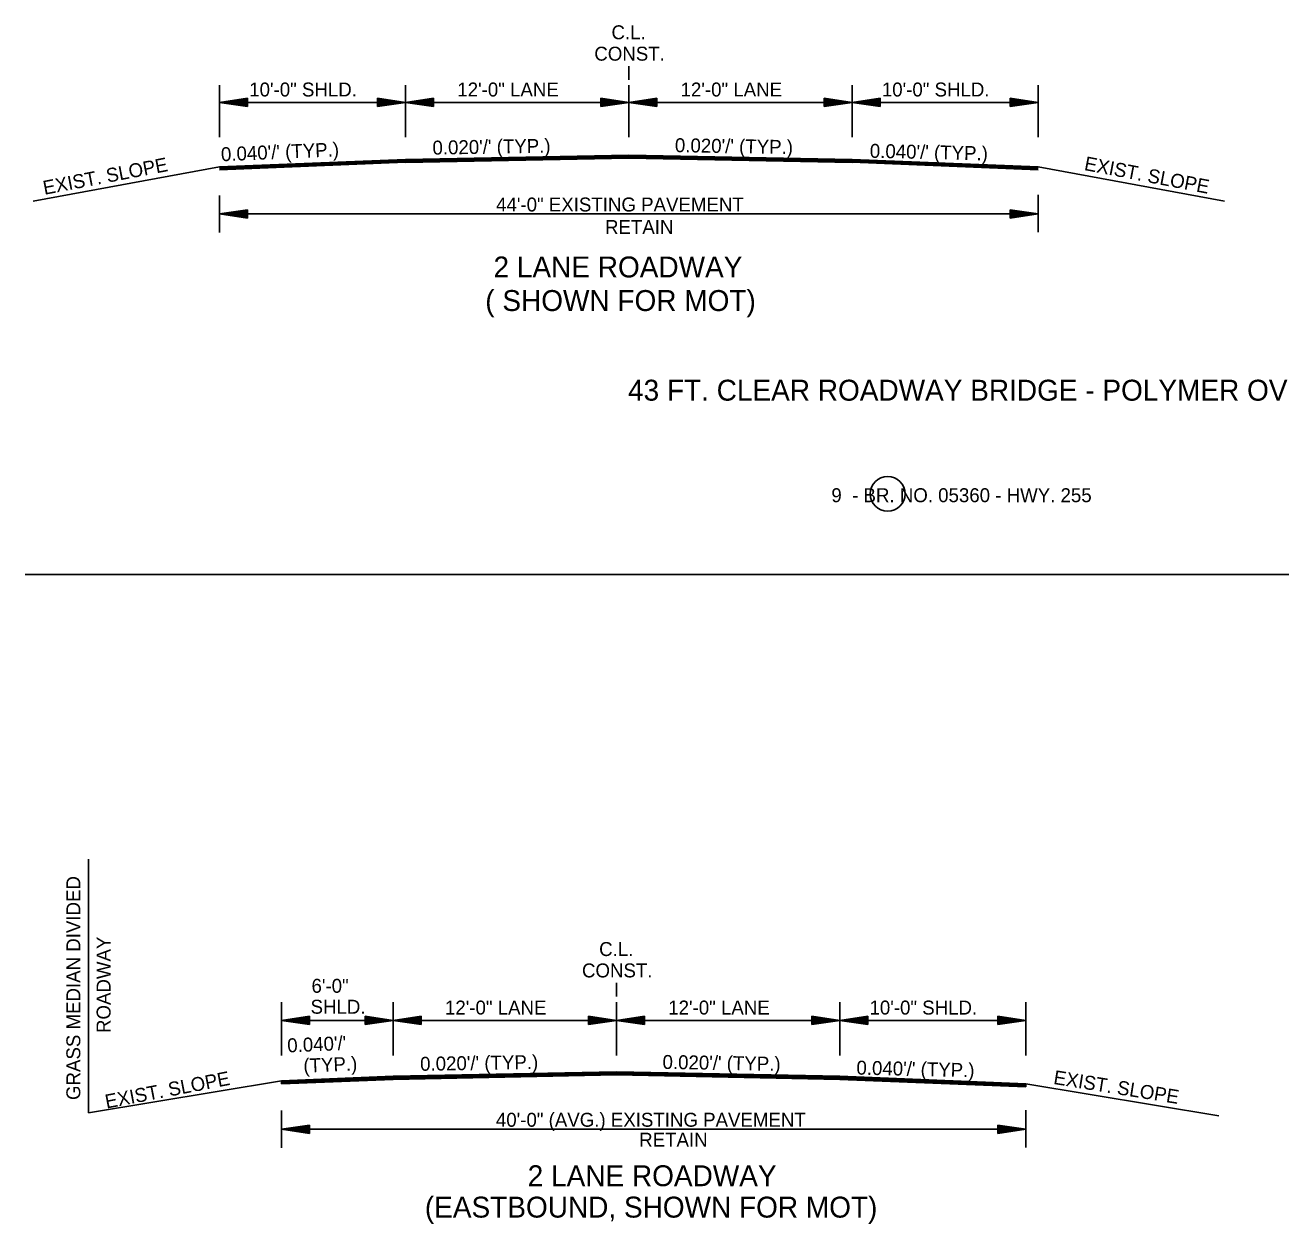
# Model space of a CAD drawing. Extents: x 550980 to 1930787, y -1972975 to 596640.
# Drawn here: x 550993 to 551668, y -1948986 to -1948341 of the extents above; entities that cross this region are included whole.
import ezdxf

# ---------------------------------------------------------------- set-up
doc = ezdxf.new("R2010")
doc.units = 0
doc.layers.add('R_Border', color=7, linetype='Continuous')
doc.layers.add('R_Draft', color=7, linetype='Continuous')

msp = doc.modelspace()

# ---------------------------------------------------------------- linework, layer by layer
at = {"layer": 'R_Border'}
for p, q in [((551317.38, -1948363.31), (551317.38, -1948370.56)), ((550992.91, -1948636.61), (552054.18, -1948636.61)), ((551027.05, -1948789.51), (551027.05, -1948925.94)), ((551310.74, -1948856.12), (551310.74, -1948863.37))]:
    msp.add_line(p, q, dxfattribs=at)
msp.add_circle((551456.48, -1948593.19), 9.34, dxfattribs=at)
at = {"layer": 'R_Draft'}
for p, q in [((551097.38, -1948401.5), (551097.38, -1948373.55)), ((551197.38, -1948401.5), (551197.38, -1948373.55)), ((551317.38, -1948401.5), (551317.38, -1948373.55)), ((551437.38, -1948401.5), (551437.38, -1948373.55)), ((551537.38, -1948401.5), (551537.38, -1948373.55)), ((551112.38, -1948380.49), (551097.38, -1948382.74)), ((551112.38, -1948380.86), (551099.88, -1948382.74)), ((551112.38, -1948381.25), (551102.46, -1948382.74)), ((551112.38, -1948381.62), (551104.96, -1948382.74)), ((551112.38, -1948382.01), (551107.5, -1948382.74)), ((551112.38, -1948380.49), (551112.38, -1948384.99)), ((551182.38, -1948380.49), (551197.38, -1948382.74)), ((551182.38, -1948380.49), (551182.38, -1948384.99)), ((551182.38, -1948380.86), (551194.87, -1948382.74)), ((551182.38, -1948381.25), (551192.29, -1948382.74)), ((551182.38, -1948381.62), (551189.8, -1948382.74)), ((551182.38, -1948382.01), (551187.25, -1948382.74)), ((551212.38, -1948380.49), (551197.38, -1948382.74)), ((551212.38, -1948380.86), (551199.88, -1948382.74)), ((551212.38, -1948381.25), (551202.46, -1948382.74)), ((551212.38, -1948381.62), (551204.96, -1948382.74)), ((551212.38, -1948382.01), (551207.5, -1948382.74)), ((551212.38, -1948380.49), (551212.38, -1948384.99)), ((551302.38, -1948380.49), (551317.38, -1948382.74)), ((551302.38, -1948380.49), (551302.38, -1948384.99)), ((551302.38, -1948380.86), (551314.87, -1948382.74)), ((551302.38, -1948381.25), (551312.29, -1948382.74)), ((551302.38, -1948381.62), (551309.8, -1948382.74)), ((551302.38, -1948382.01), (551307.25, -1948382.74)), ((551332.38, -1948380.49), (551317.38, -1948382.74)), ((551332.38, -1948380.86), (551319.88, -1948382.74)), ((551332.38, -1948381.25), (551322.46, -1948382.74)), ((551332.38, -1948381.62), (551324.96, -1948382.74)), ((551332.38, -1948382.01), (551327.5, -1948382.74)), ((551332.38, -1948380.49), (551332.38, -1948384.99)), ((551422.38, -1948380.49), (551437.38, -1948382.74)), ((551422.38, -1948380.49), (551422.38, -1948384.99)), ((551422.38, -1948380.86), (551434.87, -1948382.74)), ((551422.38, -1948381.25), (551432.29, -1948382.74)), ((551422.38, -1948381.62), (551429.8, -1948382.74)), ((551422.38, -1948382.01), (551427.25, -1948382.74)), ((551452.38, -1948380.49), (551437.38, -1948382.74)), ((551452.38, -1948380.86), (551439.88, -1948382.74)), ((551452.38, -1948381.25), (551442.46, -1948382.74)), ((551452.38, -1948381.62), (551444.96, -1948382.74)), ((551452.38, -1948382.01), (551447.5, -1948382.74)), ((551452.38, -1948380.49), (551452.38, -1948384.99)), ((551522.38, -1948380.49), (551537.38, -1948382.74)), ((551522.38, -1948380.49), (551522.38, -1948384.99)), ((551522.38, -1948380.86), (551534.87, -1948382.74)), ((551522.38, -1948381.25), (551532.29, -1948382.74)), ((551522.38, -1948381.62), (551529.8, -1948382.74)), ((551522.38, -1948382.01), (551527.25, -1948382.74)), ((551197.38, -1948382.74), (551097.38, -1948382.74)), ((551112.38, -1948384.99), (551097.38, -1948382.74)), ((551112.38, -1948384.61), (551099.88, -1948382.74)), ((551112.38, -1948384.23), (551102.46, -1948382.74)), ((551112.38, -1948383.86), (551104.96, -1948382.74)), ((551112.38, -1948383.47), (551107.5, -1948382.74)), ((551112.38, -1948382.39), (551110.01, -1948382.74)), ((551112.38, -1948383.09), (551110.01, -1948382.74)), ((551182.38, -1948382.39), (551184.75, -1948382.74)), ((551182.38, -1948384.99), (551197.38, -1948382.74)), ((551182.38, -1948383.47), (551187.25, -1948382.74)), ((551182.38, -1948384.23), (551192.29, -1948382.74)), ((551182.38, -1948384.61), (551194.87, -1948382.74)), ((551182.38, -1948383.86), (551189.8, -1948382.74)), ((551182.38, -1948383.09), (551184.75, -1948382.74)), ((551317.38, -1948382.74), (551197.38, -1948382.74)), ((551212.38, -1948384.99), (551197.38, -1948382.74)), ((551212.38, -1948384.61), (551199.88, -1948382.74)), ((551212.38, -1948384.23), (551202.46, -1948382.74)), ((551212.38, -1948383.86), (551204.96, -1948382.74)), ((551212.38, -1948383.47), (551207.5, -1948382.74)), ((551212.38, -1948382.39), (551210.01, -1948382.74)), ((551212.38, -1948383.09), (551210.01, -1948382.74)), ((551302.38, -1948382.39), (551304.75, -1948382.74)), ((551302.38, -1948384.99), (551317.38, -1948382.74)), ((551302.38, -1948383.47), (551307.25, -1948382.74)), ((551302.38, -1948384.23), (551312.29, -1948382.74)), ((551302.38, -1948384.61), (551314.87, -1948382.74)), ((551302.38, -1948383.86), (551309.8, -1948382.74)), ((551302.38, -1948383.09), (551304.75, -1948382.74)), ((551437.38, -1948382.74), (551317.38, -1948382.74)), ((551332.38, -1948384.99), (551317.38, -1948382.74)), ((551332.38, -1948384.61), (551319.88, -1948382.74)), ((551332.38, -1948384.23), (551322.46, -1948382.74)), ((551332.38, -1948383.86), (551324.96, -1948382.74)), ((551332.38, -1948383.47), (551327.5, -1948382.74)), ((551332.38, -1948382.39), (551330.01, -1948382.74)), ((551332.38, -1948383.09), (551330.01, -1948382.74)), ((551422.38, -1948382.39), (551424.75, -1948382.74)), ((551422.38, -1948384.99), (551437.38, -1948382.74)), ((551422.38, -1948383.47), (551427.25, -1948382.74)), ((551422.38, -1948384.23), (551432.29, -1948382.74)), ((551422.38, -1948384.61), (551434.87, -1948382.74)), ((551422.38, -1948383.86), (551429.8, -1948382.74)), ((551422.38, -1948383.09), (551424.75, -1948382.74)), ((551437.38, -1948382.74), (551537.38, -1948382.74)), ((551452.38, -1948384.99), (551437.38, -1948382.74)), ((551452.38, -1948384.61), (551439.88, -1948382.74)), ((551452.38, -1948384.23), (551442.46, -1948382.74)), ((551452.38, -1948383.86), (551444.96, -1948382.74)), ((551452.38, -1948383.47), (551447.5, -1948382.74)), ((551452.38, -1948382.39), (551450.01, -1948382.74)), ((551452.38, -1948383.09), (551450.01, -1948382.74)), ((551522.38, -1948382.39), (551524.75, -1948382.74)), ((551522.38, -1948384.99), (551537.38, -1948382.74)), ((551522.38, -1948383.47), (551527.25, -1948382.74)), ((551522.38, -1948384.23), (551532.29, -1948382.74)), ((551522.38, -1948384.61), (551534.87, -1948382.74)), ((551522.38, -1948383.86), (551529.8, -1948382.74)), ((551522.38, -1948383.09), (551524.75, -1948382.74)), ((551197.38, -1948413.45), (551097.38, -1948417.45)), ((551197.38, -1948413.75), (551097.38, -1948417.75)), ((551197.38, -1948414.05), (551097.38, -1948418.05)), ((551197.38, -1948414.35), (551097.38, -1948418.35)), ((551197.38, -1948414.65), (551097.38, -1948418.65)), ((551197.38, -1948414.95), (551097.38, -1948418.95)), ((551317.38, -1948411.05), (551197.38, -1948413.45)), ((551317.38, -1948411.35), (551197.38, -1948413.75)), ((551317.38, -1948411.65), (551197.38, -1948414.05)), ((551317.38, -1948411.95), (551197.38, -1948414.35)), ((551317.38, -1948412.25), (551197.38, -1948414.65)), ((551317.38, -1948412.55), (551197.38, -1948414.95)), ((551317.38, -1948412.72), (551197.38, -1948415.12)), ((551317.38, -1948411.05), (551437.38, -1948413.45)), ((551317.38, -1948411.35), (551437.38, -1948413.75)), ((551317.38, -1948411.65), (551437.38, -1948414.05)), ((551317.38, -1948411.95), (551437.38, -1948414.35)), ((551317.38, -1948412.25), (551437.38, -1948414.65)), ((551317.38, -1948412.55), (551437.38, -1948414.95)), ((551317.38, -1948412.72), (551437.38, -1948415.12)), ((551437.38, -1948413.45), (551537.38, -1948417.45)), ((551437.38, -1948413.75), (551537.38, -1948417.75)), ((551437.38, -1948414.05), (551537.38, -1948418.05)), ((551437.38, -1948414.35), (551537.38, -1948418.35)), ((551437.38, -1948414.65), (551537.38, -1948418.65)), ((551437.38, -1948414.95), (551537.38, -1948418.95)), ((551097.38, -1948417.45), (550997.31, -1948435.83)), ((551537.38, -1948417.45), (551637.45, -1948435.83)), ((551097.38, -1948432.71), (551097.38, -1948452.71)), ((551537.38, -1948432.46), (551537.38, -1948452.46)), ((551112.38, -1948440.46), (551097.38, -1948442.71)), ((551112.38, -1948444.96), (551097.38, -1948442.71)), ((551537.38, -1948442.71), (551097.38, -1948442.71)), ((551112.38, -1948440.83), (551099.88, -1948442.71)), ((551112.38, -1948444.58), (551099.88, -1948442.71)), ((551112.38, -1948441.22), (551102.46, -1948442.71)), ((551112.38, -1948444.2), (551102.46, -1948442.71)), ((551112.38, -1948441.59), (551104.96, -1948442.71)), ((551112.38, -1948443.83), (551104.96, -1948442.71)), ((551112.38, -1948441.98), (551107.5, -1948442.71)), ((551112.38, -1948443.44), (551107.5, -1948442.71)), ((551112.38, -1948442.36), (551110.01, -1948442.71)), ((551112.38, -1948443.06), (551110.01, -1948442.71)), ((551112.38, -1948440.46), (551112.38, -1948444.96)), ((551522.38, -1948440.46), (551537.38, -1948442.71)), ((551522.38, -1948444.96), (551522.38, -1948440.46)), ((551522.38, -1948440.83), (551534.87, -1948442.71)), ((551522.38, -1948441.22), (551532.29, -1948442.71)), ((551522.38, -1948441.59), (551529.8, -1948442.71)), ((551522.38, -1948441.97), (551527.25, -1948442.71)), ((551522.38, -1948442.36), (551524.75, -1948442.71)), ((551522.38, -1948444.96), (551537.38, -1948442.71)), ((551522.38, -1948443.44), (551527.25, -1948442.71)), ((551522.38, -1948444.2), (551532.29, -1948442.71)), ((551522.38, -1948444.58), (551534.87, -1948442.71)), ((551522.38, -1948443.83), (551529.8, -1948442.71)), ((551522.38, -1948443.06), (551524.75, -1948442.71)), ((551130.74, -1948895.08), (551130.74, -1948866.36)), ((551190.74, -1948895.08), (551190.74, -1948866.36)), ((551310.74, -1948895.08), (551310.74, -1948866.36)), ((551430.74, -1948895.08), (551430.74, -1948866.36)), ((551530.74, -1948895.08), (551530.74, -1948866.36)), ((551145.74, -1948874.01), (551130.74, -1948876.26)), ((551145.74, -1948874.38), (551133.24, -1948876.26)), ((551145.74, -1948874.76), (551135.82, -1948876.26)), ((551145.74, -1948874.01), (551145.74, -1948878.51)), ((551175.74, -1948874.01), (551190.74, -1948876.26)), ((551175.74, -1948878.51), (551175.74, -1948874.01)), ((551175.74, -1948874.38), (551188.23, -1948876.26)), ((551175.74, -1948874.76), (551185.65, -1948876.26)), ((551205.74, -1948874.01), (551190.74, -1948876.26)), ((551205.74, -1948874.38), (551193.24, -1948876.26)), ((551205.74, -1948874.76), (551195.82, -1948876.26)), ((551205.74, -1948874.01), (551205.74, -1948878.51)), ((551295.74, -1948874.01), (551310.74, -1948876.26)), ((551295.74, -1948878.51), (551295.74, -1948874.01)), ((551295.74, -1948874.38), (551308.23, -1948876.26)), ((551295.74, -1948874.76), (551305.65, -1948876.26)), ((551325.74, -1948874.01), (551310.74, -1948876.26)), ((551325.74, -1948874.38), (551313.24, -1948876.26)), ((551325.74, -1948874.76), (551315.82, -1948876.26)), ((551325.74, -1948874.01), (551325.74, -1948878.51)), ((551415.74, -1948874.01), (551430.74, -1948876.26)), ((551415.74, -1948878.51), (551415.74, -1948874.01)), ((551415.74, -1948874.38), (551428.23, -1948876.26)), ((551415.74, -1948874.76), (551425.65, -1948876.26)), ((551445.74, -1948874.01), (551430.74, -1948876.26)), ((551445.74, -1948874.38), (551433.24, -1948876.26)), ((551445.74, -1948874.76), (551435.82, -1948876.26)), ((551445.74, -1948874.01), (551445.74, -1948878.51)), ((551515.74, -1948874.01), (551530.74, -1948876.26)), ((551515.74, -1948878.51), (551515.74, -1948874.01)), ((551515.74, -1948874.38), (551528.24, -1948876.26)), ((551515.74, -1948874.76), (551525.66, -1948876.26)), ((551145.74, -1948878.51), (551130.74, -1948876.26)), ((551190.74, -1948876.26), (551130.74, -1948876.26)), ((551145.74, -1948878.13), (551133.24, -1948876.26)), ((551145.74, -1948877.75), (551135.82, -1948876.26)), ((551145.74, -1948875.14), (551138.32, -1948876.26)), ((551145.74, -1948877.37), (551138.32, -1948876.26)), ((551145.74, -1948875.53), (551140.86, -1948876.26)), ((551145.74, -1948876.99), (551140.86, -1948876.26)), ((551145.74, -1948875.9), (551143.37, -1948876.26)), ((551145.74, -1948876.61), (551143.37, -1948876.26)), ((551175.74, -1948875.14), (551183.16, -1948876.26)), ((551175.74, -1948875.52), (551180.61, -1948876.26)), ((551175.74, -1948875.9), (551178.11, -1948876.26)), ((551175.74, -1948878.51), (551190.74, -1948876.26)), ((551175.74, -1948876.98), (551180.61, -1948876.26)), ((551175.74, -1948877.75), (551185.65, -1948876.26)), ((551175.74, -1948878.13), (551188.23, -1948876.26)), ((551175.74, -1948877.37), (551183.16, -1948876.26)), ((551175.74, -1948876.61), (551178.11, -1948876.26)), ((551190.74, -1948876.26), (551310.74, -1948876.26)), ((551205.74, -1948878.51), (551190.74, -1948876.26)), ((551205.74, -1948878.13), (551193.24, -1948876.26)), ((551205.74, -1948877.75), (551195.82, -1948876.26)), ((551205.74, -1948875.14), (551198.32, -1948876.26)), ((551205.74, -1948877.37), (551198.32, -1948876.26)), ((551205.74, -1948875.53), (551200.86, -1948876.26)), ((551205.74, -1948876.99), (551200.86, -1948876.26)), ((551205.74, -1948875.9), (551203.37, -1948876.26)), ((551205.74, -1948876.61), (551203.37, -1948876.26)), ((551295.74, -1948875.14), (551303.16, -1948876.26)), ((551295.74, -1948875.52), (551300.61, -1948876.26)), ((551295.74, -1948875.9), (551298.11, -1948876.26)), ((551295.74, -1948878.51), (551310.74, -1948876.26)), ((551295.74, -1948876.98), (551300.61, -1948876.26)), ((551295.74, -1948877.75), (551305.65, -1948876.26)), ((551295.74, -1948878.13), (551308.23, -1948876.26)), ((551295.74, -1948877.37), (551303.16, -1948876.26)), ((551295.74, -1948876.61), (551298.11, -1948876.26)), ((551310.74, -1948876.26), (551430.74, -1948876.26)), ((551325.74, -1948878.51), (551310.74, -1948876.26)), ((551325.74, -1948878.13), (551313.24, -1948876.26)), ((551325.74, -1948877.75), (551315.82, -1948876.26)), ((551325.74, -1948875.14), (551318.32, -1948876.26)), ((551325.74, -1948877.37), (551318.32, -1948876.26)), ((551325.74, -1948875.53), (551320.86, -1948876.26)), ((551325.74, -1948876.99), (551320.86, -1948876.26)), ((551325.74, -1948875.9), (551323.37, -1948876.26)), ((551325.74, -1948876.61), (551323.37, -1948876.26)), ((551415.74, -1948875.14), (551423.16, -1948876.26)), ((551415.74, -1948875.52), (551420.61, -1948876.26)), ((551415.74, -1948875.9), (551418.11, -1948876.26)), ((551415.74, -1948878.51), (551430.74, -1948876.26)), ((551415.74, -1948876.98), (551420.61, -1948876.26)), ((551415.74, -1948877.75), (551425.65, -1948876.26)), ((551415.74, -1948878.13), (551428.23, -1948876.26)), ((551415.74, -1948877.37), (551423.16, -1948876.26)), ((551415.74, -1948876.61), (551418.11, -1948876.26)), ((551430.74, -1948876.26), (551530.74, -1948876.26)), ((551445.74, -1948878.51), (551430.74, -1948876.26)), ((551445.74, -1948878.13), (551433.24, -1948876.26)), ((551445.74, -1948877.75), (551435.82, -1948876.26)), ((551445.74, -1948875.14), (551438.32, -1948876.26)), ((551445.74, -1948877.37), (551438.32, -1948876.26)), ((551445.74, -1948875.53), (551440.86, -1948876.26)), ((551445.74, -1948876.99), (551440.86, -1948876.26)), ((551445.74, -1948875.9), (551443.37, -1948876.26)), ((551445.74, -1948876.61), (551443.37, -1948876.26)), ((551515.74, -1948875.14), (551523.16, -1948876.26)), ((551515.74, -1948875.52), (551520.62, -1948876.26)), ((551515.74, -1948875.9), (551518.11, -1948876.26)), ((551515.74, -1948878.51), (551530.74, -1948876.26)), ((551515.74, -1948876.98), (551520.62, -1948876.26)), ((551515.74, -1948877.75), (551525.66, -1948876.26)), ((551515.74, -1948878.13), (551528.24, -1948876.26)), ((551515.74, -1948877.37), (551523.16, -1948876.26)), ((551515.74, -1948876.61), (551518.11, -1948876.26)), ((551130.74, -1948908.66), (551027.05, -1948925.94)), ((551190.74, -1948906.26), (551130.74, -1948908.66)), ((551190.74, -1948906.56), (551130.74, -1948908.96)), ((551190.74, -1948906.86), (551130.74, -1948909.26)), ((551190.74, -1948907.16), (551130.74, -1948909.56)), ((551190.74, -1948907.46), (551130.74, -1948909.86)), ((551190.74, -1948907.76), (551130.74, -1948910.16)), ((551190.74, -1948907.93), (551130.74, -1948910.33)), ((551130.74, -1948910.33), (551130.74, -1948908.66)), ((551310.74, -1948903.86), (551190.74, -1948906.26)), ((551310.74, -1948904.16), (551190.74, -1948906.56)), ((551310.74, -1948904.46), (551190.74, -1948906.86)), ((551310.74, -1948904.76), (551190.74, -1948907.16)), ((551310.74, -1948905.06), (551190.74, -1948907.46)), ((551310.74, -1948905.36), (551190.74, -1948907.76)), ((551310.74, -1948905.53), (551190.74, -1948907.93)), ((551310.74, -1948903.86), (551430.74, -1948906.26)), ((551310.74, -1948904.16), (551430.74, -1948906.56)), ((551310.74, -1948904.46), (551430.74, -1948906.86)), ((551310.74, -1948904.76), (551430.74, -1948907.16)), ((551310.74, -1948905.06), (551430.74, -1948907.46)), ((551310.74, -1948905.36), (551430.74, -1948907.76)), ((551310.74, -1948905.53), (551430.74, -1948907.93)), ((551430.74, -1948906.26), (551530.74, -1948910.26)), ((551430.74, -1948906.56), (551530.74, -1948910.56)), ((551430.74, -1948906.86), (551530.74, -1948910.86)), ((551430.74, -1948907.16), (551530.74, -1948911.16)), ((551430.74, -1948907.46), (551530.74, -1948911.46)), ((551430.74, -1948907.76), (551530.74, -1948911.76)), ((551430.74, -1948907.93), (551530.74, -1948911.93)), ((551530.74, -1948910.26), (551634.42, -1948927.54)), ((551530.74, -1948911.93), (551530.74, -1948910.26)), ((551130.74, -1948924.72), (551130.74, -1948944.72)), ((551530.74, -1948924.47), (551530.74, -1948944.47)), ((551145.74, -1948932.47), (551130.74, -1948934.72)), ((551145.74, -1948936.97), (551130.74, -1948934.72)), ((551530.74, -1948934.72), (551130.74, -1948934.72)), ((551145.74, -1948932.85), (551133.24, -1948934.72)), ((551145.74, -1948936.6), (551133.24, -1948934.72)), ((551145.74, -1948933.23), (551135.82, -1948934.72)), ((551145.74, -1948936.21), (551135.82, -1948934.72)), ((551145.74, -1948933.6), (551138.32, -1948934.72)), ((551145.74, -1948935.84), (551138.32, -1948934.72)), ((551145.74, -1948933.99), (551140.86, -1948934.72)), ((551145.74, -1948935.46), (551140.86, -1948934.72)), ((551145.74, -1948934.37), (551143.37, -1948934.72)), ((551145.74, -1948935.07), (551143.37, -1948934.72)), ((551145.74, -1948932.47), (551145.74, -1948936.97)), ((551515.74, -1948932.47), (551530.74, -1948934.72)), ((551515.74, -1948936.97), (551515.74, -1948932.47)), ((551515.74, -1948932.85), (551528.24, -1948934.72)), ((551515.74, -1948933.23), (551525.66, -1948934.72)), ((551515.74, -1948933.6), (551523.16, -1948934.72)), ((551515.74, -1948933.99), (551520.62, -1948934.72)), ((551515.74, -1948934.37), (551518.11, -1948934.72)), ((551515.74, -1948936.97), (551530.74, -1948934.72)), ((551515.74, -1948935.45), (551520.62, -1948934.72)), ((551515.74, -1948936.21), (551525.66, -1948934.72)), ((551515.74, -1948936.6), (551528.24, -1948934.72)), ((551515.74, -1948935.84), (551523.16, -1948934.72)), ((551515.74, -1948935.07), (551518.11, -1948934.72))]:
    msp.add_line(p, q, dxfattribs=at)

# ---------------------------------------------------------------- texts
at = {"layer": 'R_Border'}
for s, height, p in [('C.L.', 7.5, (551308.05, -1948348.81)), ('CONST.', 7.5, (551298.83, -1948360.31)), ('( SHOWN FOR MOT)', 11.25, (551240.21, -1948494.89)), ('C.L.', 7.5, (551301.41, -1948841.62)), ('CONST.', 7.5, (551292.2, -1948853.12))]:
    msp.add_text(s, height=height, dxfattribs=at).set_placement(p)
for s, p in [('GRASS MEDIAN DIVIDED', (551022.57, -1948919.01)), ('ROADWAY', (551038.83, -1948883.01))]:
    msp.add_text(s, height=7.5, rotation=90, dxfattribs=at).set_placement(p)
at = {"layer": 'R_Draft'}
for s, height, p in [('10\'-0" SHLD.', 7.5, (551113.36, -1948379.57)), ('12\'-0" LANE', 7.5, (551225.19, -1948379.57)), ('12\'-0" LANE', 7.5, (551345.19, -1948379.57)), ('10\'-0" SHLD.', 7.5, (551453.36, -1948379.57)), ('44\'-0" EXISTING PAVEMENT ', 7.5, (551246.05, -1948441.39)), ('RETAIN', 7.5, (551304.57, -1948453.48)), ('2 LANE ROADWAY', 11.25, (551244.65, -1948476.84)), ('43 FT. CLEAR ROADWAY BRIDGE - POLYMER OVERLAY', 11.25, (551316.94, -1948543.08)), ('      9  - BR. NO. 05360 - HWY. 255', 7.5, (551409.51, -1948597.65)), ('6\'-0"', 7.5, (551146.83, -1948861.39)), ('SHLD.', 7.5, (551146.33, -1948872.64)), ('12\'-0" LANE', 7.5, (551218.56, -1948873.08)), ('12\'-0" LANE', 7.5, (551338.56, -1948873.08)), ('10\'-0" SHLD.', 7.5, (551446.72, -1948873.08)), ('40\'-0" (AVG.) EXISTING PAVEMENT', 7.5, (551245.94, -1948933.4)), ('RETAIN', 7.5, (551322.95, -1948944.12)), ('2 LANE ROADWAY ', 11.25, (551263.02, -1948965.36)), ('(EASTBOUND, SHOWN FOR MOT)', 11.25, (551207.75, -1948982.23))]:
    msp.add_text(s, height=height, dxfattribs=at).set_placement(p)
for s, rotation, p in [("0.020'/' (TYP.)", 0.97192, (551211.9, -1948410.84)), ("0.020'/' (TYP.)", 359.02808, (551342.08, -1948409.47)), ("  0.040'/' (TYP.)", 2.44797, (551092.76, -1948414.65)), ("0.040'/' (TYP.)", 358.68162, (551446.82, -1948412.48)), ('EXIST. SLOPE', 10.88286, (551003.29, -1948432.45)), ('EXIST. SLOPE', 349.11714, (551561.76, -1948419.05)), ("  0.040'/'", 2.44797, (551128.39, -1948893.69)), ("0.020'/' (TYP.)", 0.97192, (551205.26, -1948903.36)), ("0.020'/' (TYP.)", 359.02808, (551335.44, -1948902.29)), (' (TYP.)', 2.44797, (551139.82, -1948904.46)), ("0.040'/' (TYP.)", 358.68162, (551439.63, -1948905.34)), ('EXIST. SLOPE', 10.88286, (551036.65, -1948923.66)), ('EXIST. SLOPE', 350.84656, (551545.27, -1948910.36))]:
    msp.add_text(s, height=7.5, rotation=rotation, dxfattribs=at).set_placement(p)

doc.saveas('drawing.dxf')
